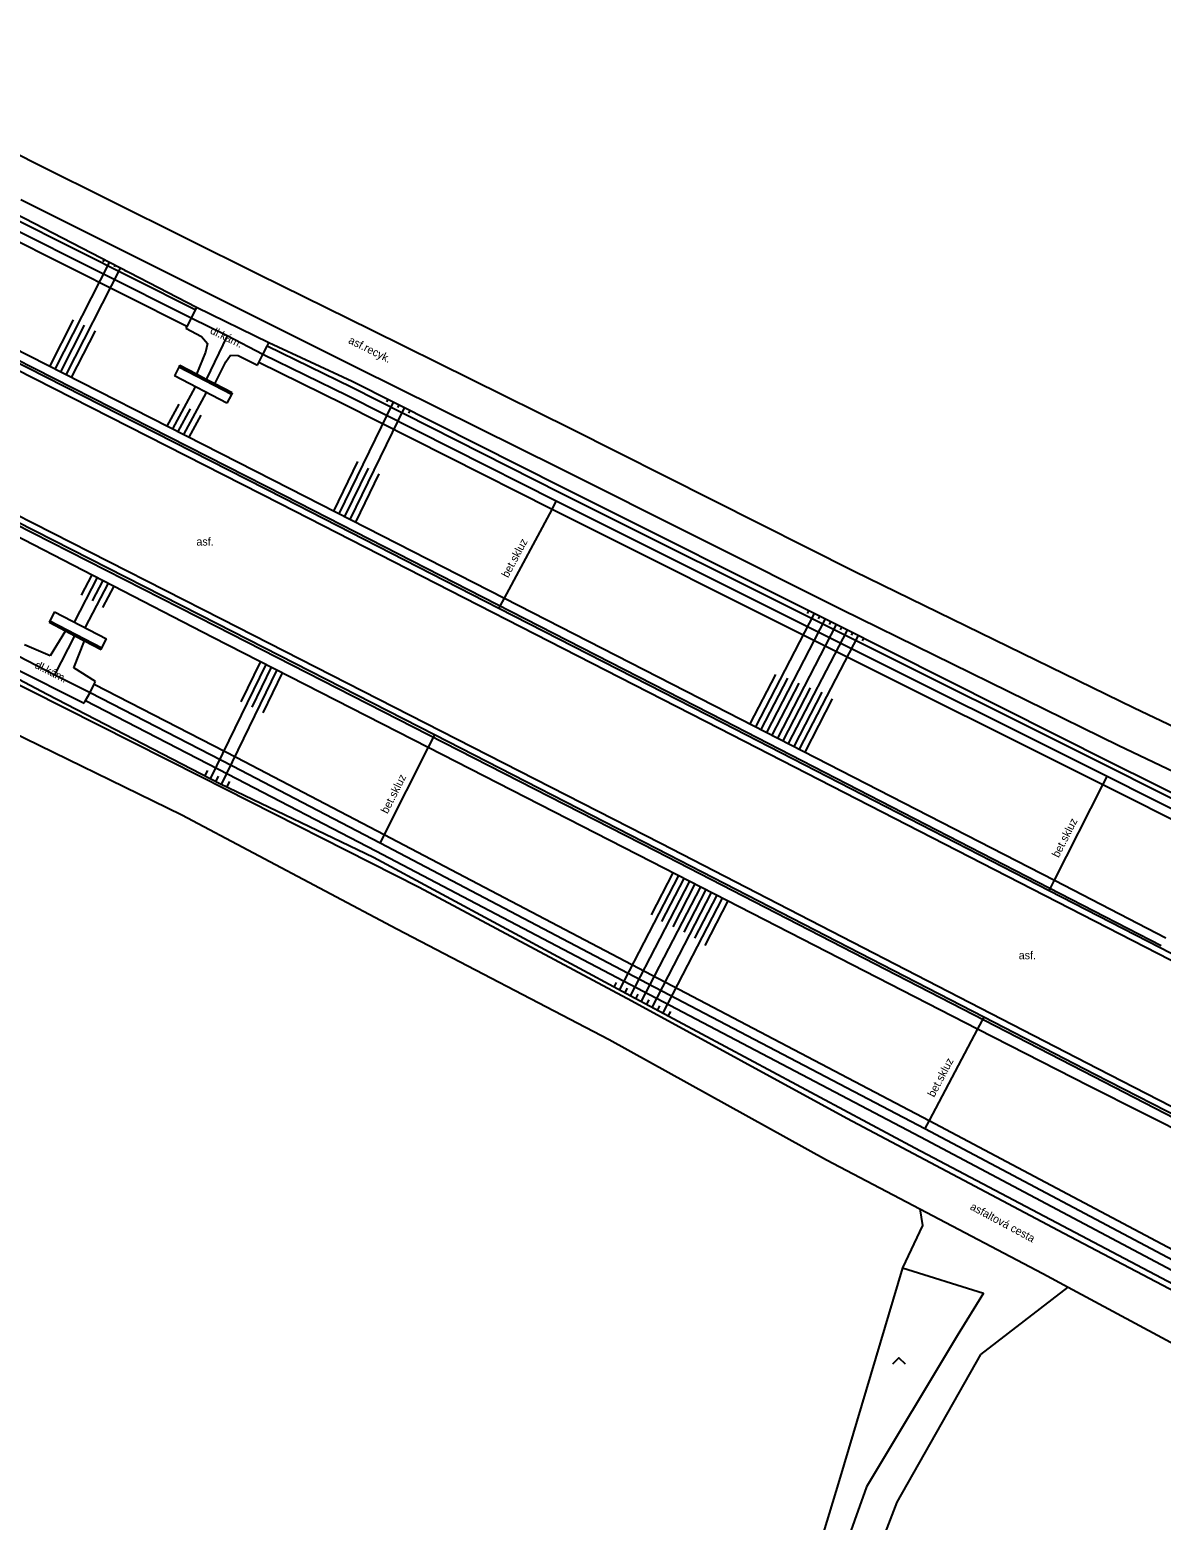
# Model space of a CAD drawing. Extents: x -539244 to -537359, y -1183785 to -1181851.
# Drawn here: x -538474.3 to -538382.4, y -1182902.8 to -1182781.7 of the extents above; entities that cross this region are included whole.
import ezdxf

# ---------------------------------------------------------------- set-up
doc = ezdxf.new("R2010")
doc.units = 0
for name, color, linetype in [('Vrstva 10', 7, 'Continuous'), ('Vrstva 11', 7, 'Continuous'), ('Vrstva 14', 7, 'Continuous'), ('Vrstva 15', 7, 'Continuous'), ('Vrstva 21', 7, 'Continuous'), ('Vrstva 36', 7, 'Continuous'), ('Vrstva 40', 7, 'Continuous'), ('Vrstva 9', 7, 'Continuous')]:
    doc.layers.add(name, color=color, linetype=linetype)

msp = doc.modelspace()

# ---------------------------------------------------------------- linework, layer by layer
at = {"layer": 'Vrstva 10'}
for p, q in [((-538489.631, -1182802.063), (-538453.977, -1182820.153)), ((-538458.743, -1182829.553), (-538494.407, -1182811.446)), ((-538453.977, -1182820.153), (-538418.301, -1182838.412)), ((-538423.066, -1182847.775), (-538458.743, -1182829.553)), ((-538418.301, -1182838.412), (-538382.698, -1182856.699)), ((-538387.534, -1182866.074), (-538423.066, -1182847.775)), ((-538382.698, -1182856.699), (-538347.199, -1182875.039)), ((-538351.928, -1182884.425), (-538387.534, -1182866.074))]:
    msp.add_line(p, q, dxfattribs=at)
at = {"layer": 'Vrstva 11'}
for p, q in [((-538495.381, -1182781.683), (-538473.693, -1182792.597)), ((-538473.693, -1182792.597), (-538455.751, -1182801.544)), ((-538457.128, -1182804.455), (-538475.061, -1182795.493)), ((-538460.885, -1182804.439), (-538475.768, -1182796.967)), ((-538461.569, -1182805.774), (-538476.446, -1182798.305)), ((-538455.751, -1182801.544), (-538446.57, -1182806.067)), ((-538454.912, -1182807.118), (-538460.787, -1182804.249)), ((-538447.711, -1182809.176), (-538457.128, -1182804.455)), ((-538461.642, -1182805.916), (-538460.386, -1182806.606)), ((-538446.57, -1182806.067), (-538430.372, -1182814.08)), ((-538460.386, -1182806.606), (-538459.885, -1182807.165)), ((-538459.885, -1182807.165), (-538460.05, -1182807.864)), ((-538448.175, -1182810.748), (-538455.046, -1182807.382)), ((-538460.05, -1182807.864), (-538460.797, -1182809.658)), ((-538459.29, -1182810.442), (-538458.395, -1182808.642)), ((-538458.395, -1182808.642), (-538458.033, -1182808.1)), ((-538458.033, -1182808.1), (-538457.395, -1182808.131)), ((-538457.395, -1182808.131), (-538455.829, -1182808.93)), ((-538448.843, -1182812.092), (-538455.723, -1182808.721)), ((-538458.322, -1182812.015), (-538462.579, -1182809.803)), ((-538457.953, -1182811.305), (-538462.21, -1182809.093)), ((-538431.382, -1182817.268), (-538447.711, -1182809.176)), ((-538431.213, -1182819.315), (-538448.175, -1182810.748)), ((-538431.887, -1182820.655), (-538448.843, -1182812.092)), ((-538430.372, -1182814.08), (-538407.338, -1182825.669)), ((-538408.354, -1182828.793), (-538431.382, -1182817.268)), ((-538408.747, -1182830.537), (-538431.213, -1182819.315)), ((-538409.417, -1182831.879), (-538431.887, -1182820.655)), ((-538407.338, -1182825.669), (-538384.592, -1182836.775)), ((-538472.33, -1182828.973), (-538468.1, -1182831.168)), ((-538385.827, -1182839.854), (-538408.354, -1182828.793)), ((-538472.699, -1182829.683), (-538468.469, -1182831.878)), ((-538471.442, -1182830.504), (-538472.667, -1182832.544)), ((-538386.455, -1182841.675), (-538408.747, -1182830.537)), ((-538472.667, -1182832.544), (-538474.756, -1182831.645)), ((-538470.753, -1182833.522), (-538469.885, -1182831.312)), ((-538387.127, -1182843.017), (-538409.417, -1182831.879)), ((-538460.441, -1182842.376), (-538477.999, -1182833.509)), ((-538475.727, -1182833.456), (-538469.918, -1182836.378)), ((-538468.983, -1182834.631), (-538470.753, -1182833.522)), ((-538469.096, -1182834.841), (-538457.517, -1182840.808)), ((-538469.804, -1182836.165), (-538458.207, -1182842.14)), ((-538384.592, -1182836.775), (-538361.115, -1182847.877)), ((-538479.69, -1182836.826), (-538461.985, -1182845.451)), ((-538362.461, -1182850.949), (-538385.827, -1182839.854)), ((-538457.517, -1182840.808), (-538445.524, -1182847.048)), ((-538442.702, -1182851.367), (-538460.441, -1182842.376)), ((-538458.207, -1182842.14), (-538446.209, -1182848.383)), ((-538363.328, -1182853.284), (-538386.455, -1182841.675)), ((-538364.002, -1182854.624), (-538387.127, -1182843.017)), ((-538461.985, -1182845.451), (-538444.501, -1182854.716)), ((-538445.524, -1182847.048), (-538424.319, -1182858.183)), ((-538446.209, -1182848.383), (-538425.015, -1182859.511)), ((-538425.404, -1182860.593), (-538442.702, -1182851.367)), ((-538444.501, -1182854.716), (-538427.254, -1182863.712)), ((-538424.319, -1182858.183), (-538401.242, -1182870.277)), ((-538425.015, -1182859.511), (-538401.942, -1182871.603)), ((-538407.94, -1182870.134), (-538425.404, -1182860.593)), ((-538427.254, -1182863.712), (-538409.594, -1182873.474)), ((-538352.202, -1182884.876), (-538387.783, -1182866.536)), ((-538390.295, -1182879.474), (-538407.94, -1182870.134)), ((-538401.242, -1182870.277), (-538379.033, -1182882.058)), ((-538401.942, -1182871.603), (-538379.737, -1182883.384)), ((-538373.288, -1182888.418), (-538390.295, -1182879.474)), ((-538403.42, -1182882.26), (-538396.84, -1182884.3)), ((-538397.04, -1182889.29), (-538389.965, -1182883.816)), ((-538396.84, -1182884.3), (-538398.97, -1182887.78)), ((-538398.97, -1182887.78), (-538406.33, -1182900.03)), ((-538403.86, -1182901.3), (-538397.04, -1182889.29)), ((-538406.33, -1182900.03), (-538415.89, -1182926.8)), ((-538413.81, -1182927.3), (-538403.86, -1182901.3))]:
    msp.add_line(p, q, dxfattribs=at)
for points in [[(-538453.722, -1182819.731), (-538480.448, -1182806.147), (-538489.405, -1182801.595)], [(-538460.787, -1182804.249), (-538460.885, -1182804.439), (-538461.208, -1182805.116), (-538461.569, -1182805.774), (-538461.642, -1182805.916)], [(-538455.829, -1182808.93), (-538455.723, -1182808.721), (-538455.392, -1182808.048), (-538455.046, -1182807.382), (-538454.912, -1182807.118)], [(-538462.141, -1182808.96), (-538462.21, -1182809.093), (-538462.579, -1182809.803)], [(-538457.884, -1182811.172), (-538459.29, -1182810.442), (-538459.992, -1182810.077), (-538460.797, -1182809.658), (-538462.141, -1182808.96)], [(-538457.884, -1182811.172), (-538457.953, -1182811.305), (-538458.322, -1182812.015)], [(-538459.1, -1182829.941), (-538485.794, -1182816.371), (-538494.666, -1182811.861)], [(-538418.052, -1182837.967), (-538436.208, -1182828.685), (-538453.722, -1182819.731)], [(-538472.33, -1182828.973), (-538472.699, -1182829.683), (-538472.768, -1182829.816)], [(-538472.768, -1182829.816), (-538471.442, -1182830.504), (-538470.671, -1182830.904), (-538469.885, -1182831.312), (-538468.538, -1182832.011)], [(-538423.368, -1182848.208), (-538441.45, -1182838.964), (-538459.1, -1182829.941)], [(-538468.538, -1182832.011), (-538468.469, -1182831.878), (-538468.1, -1182831.168)], [(-538469.918, -1182836.378), (-538469.804, -1182836.165), (-538469.419, -1182835.519), (-538469.096, -1182834.841), (-538468.983, -1182834.631)], [(-538382.485, -1182856.261), (-538391.507, -1182851.621), (-538418.052, -1182837.967)], [(-538387.783, -1182866.536), (-538396.812, -1182861.886), (-538423.368, -1182848.208)], [(-538346.958, -1182874.603), (-538346.996, -1182874.583), (-538382.485, -1182856.261)], [(-538409.594, -1182873.474), (-538402.011, -1182877.46), (-538392.009, -1182882.718)], [(-538402.011, -1182877.46), (-538401.79, -1182878.82), (-538403.42, -1182882.26)], [(-538392.009, -1182882.718), (-538389.965, -1182883.816), (-538375.09, -1182891.807)]]:
    msp.add_lwpolyline(points, dxfattribs=at)
at = {"layer": 'Vrstva 14'}
for p, q in [((-538460.787, -1182804.249), (-538475.557, -1182796.594)), ((-538461.208, -1182805.116), (-538476.105, -1182797.637)), ((-538458.297, -1182806.536), (-538461.208, -1182805.116)), ((-538458.297, -1182806.536), (-538459.992, -1182810.077)), ((-538455.392, -1182808.048), (-538458.297, -1182806.536)), ((-538448.13, -1182810.251), (-538454.912, -1182807.118)), ((-538448.509, -1182811.42), (-538455.392, -1182808.048)), ((-538431.098, -1182818.824), (-538448.13, -1182810.251)), ((-538431.55, -1182819.985), (-538448.509, -1182811.42)), ((-538408.793, -1182829.99), (-538431.098, -1182818.824)), ((-538409.082, -1182831.208), (-538431.55, -1182819.985)), ((-538472.928, -1182835.682), (-538490.861, -1182826.18)), ((-538436.208, -1182828.685), (-538435.764, -1182827.856)), ((-538386.446, -1182841.225), (-538408.793, -1182829.99)), ((-538472.302, -1182834.08), (-538470.671, -1182830.904)), ((-538386.791, -1182842.346), (-538409.082, -1182831.208)), ((-538475.264, -1182832.53), (-538472.302, -1182834.08)), ((-538472.302, -1182834.08), (-538469.419, -1182835.519)), ((-538469.419, -1182835.519), (-538457.862, -1182841.474)), ((-538458.844, -1182842.954), (-538472.928, -1182835.682)), ((-538441.45, -1182838.964), (-538441.956, -1182839.968)), ((-538441.956, -1182839.968), (-538445.524, -1182847.048)), ((-538457.862, -1182841.474), (-538445.862, -1182847.718)), ((-538363.414, -1182852.724), (-538386.446, -1182841.225)), ((-538363.665, -1182853.954), (-538386.791, -1182842.346)), ((-538446.41, -1182848.907), (-538458.844, -1182842.954)), ((-538445.524, -1182847.048), (-538445.862, -1182847.718)), ((-538445.862, -1182847.718), (-538424.667, -1182858.847)), ((-538425.493, -1182860.19), (-538446.41, -1182848.907)), ((-538391.507, -1182851.621), (-538391.076, -1182850.773)), ((-538424.667, -1182858.847), (-538401.592, -1182870.94)), ((-538402.421, -1182872.533), (-538425.493, -1182860.19)), ((-538396.812, -1182861.886), (-538397.311, -1182862.832)), ((-538388.26, -1182867.47), (-538352.414, -1182885.451)), ((-538401.592, -1182870.94), (-538379.385, -1182882.721)), ((-538380.364, -1182884.152), (-538402.421, -1182872.533))]:
    msp.add_line(p, q, dxfattribs=at)
for points in [[(-538488.966, -1182800.758), (-538480.02, -1182805.308), (-538453.209, -1182818.943)], [(-538495.104, -1182812.627), (-538486.219, -1182817.21), (-538459.455, -1182831.015)], [(-538453.209, -1182818.943), (-538435.764, -1182827.856), (-538417.613, -1182837.129)], [(-538435.764, -1182827.856), (-538431.887, -1182820.655), (-538431.55, -1182819.985)], [(-538459.455, -1182831.015), (-538441.956, -1182839.968), (-538423.803, -1182849.256)], [(-538417.613, -1182837.129), (-538391.076, -1182850.773), (-538382.012, -1182855.433)], [(-538391.076, -1182850.773), (-538387.127, -1182843.017), (-538386.791, -1182842.346)], [(-538423.803, -1182849.256), (-538397.311, -1182862.832), (-538388.26, -1182867.47)], [(-538397.311, -1182862.832), (-538401.242, -1182870.277), (-538401.592, -1182870.94)]]:
    msp.add_lwpolyline(points, dxfattribs=at)
at = {"layer": 'Vrstva 15'}
for p, q in [((-538468.373, -1182800.513), (-538468.294, -1182800.358)), ((-538472.269, -1182809.25), (-538467.849, -1182800.589)), ((-538471.378, -1182809.703), (-538466.962, -1182801.049)), ((-538467.462, -1182800.93), (-538467.405, -1182800.819)), ((-538466.557, -1182801.357), (-538466.517, -1182801.279)), ((-538472.715, -1182809.023), (-538470.792, -1182805.255)), ((-538471.823, -1182809.476), (-538469.888, -1182805.684)), ((-538470.931, -1182809.93), (-538468.996, -1182806.137)), ((-538460.897, -1182810.677), (-538462.738, -1182814.097)), ((-538460.01, -1182811.138), (-538461.847, -1182814.55)), ((-538462.224, -1182812.085), (-538463.184, -1182813.87)), ((-538461.294, -1182812.469), (-538462.292, -1182814.324)), ((-538449.179, -1182821.002), (-538444.773, -1182811.941)), ((-538448.288, -1182821.457), (-538443.879, -1182812.391)), ((-538445.312, -1182811.908), (-538445.219, -1182811.716)), ((-538444.419, -1182812.358), (-538444.326, -1182812.166)), ((-538460.435, -1182812.984), (-538461.4, -1182814.777)), ((-538443.536, -1182812.827), (-538443.433, -1182812.615)), ((-538449.624, -1182820.775), (-538447.67, -1182816.757)), ((-538448.733, -1182821.23), (-538446.82, -1182817.297)), ((-538447.843, -1182821.685), (-538445.937, -1182817.765)), ((-538470.712, -1182829.813), (-538468.822, -1182826.183)), ((-538470.131, -1182827.614), (-538469.267, -1182825.954)), ((-538469.825, -1182830.273), (-538467.934, -1182826.641)), ((-538469.247, -1182828.081), (-538468.378, -1182826.412)), ((-538468.393, -1182828.606), (-538467.489, -1182826.871)), ((-538415.338, -1182838.299), (-538410.575, -1182829.098)), ((-538411.138, -1182829.097), (-538411.023, -1182828.874)), ((-538410.24, -1182829.539), (-538410.128, -1182829.322)), ((-538414.449, -1182838.756), (-538409.681, -1182829.545)), ((-538413.559, -1182839.213), (-538408.787, -1182829.993)), ((-538412.67, -1182839.67), (-538407.894, -1182830.442)), ((-538409.343, -1182829.98), (-538409.234, -1182829.769)), ((-538408.446, -1182830.422), (-538408.34, -1182830.218)), ((-538407.549, -1182830.865), (-538407.447, -1182830.667)), ((-538411.781, -1182840.127), (-538407, -1182830.891)), ((-538406.659, -1182831.318), (-538406.554, -1182831.116)), ((-538457.156, -1182836.264), (-538455.57, -1182833.003)), ((-538459.652, -1182842.537), (-538455.126, -1182833.23)), ((-538458.761, -1182842.994), (-538454.235, -1182833.686)), ((-538456.262, -1182836.711), (-538454.68, -1182833.458)), ((-538455.373, -1182837.168), (-538453.79, -1182833.913)), ((-538415.783, -1182838.07), (-538413.705, -1182834.056)), ((-538414.893, -1182838.527), (-538412.735, -1182834.358)), ((-538414.004, -1182838.984), (-538411.811, -1182834.747)), ((-538413.115, -1182839.442), (-538410.881, -1182835.126)), ((-538412.226, -1182839.899), (-538409.941, -1182835.486)), ((-538411.337, -1182840.356), (-538409.103, -1182836.04)), ((-538460.096, -1182842.308), (-538459.87, -1182841.844)), ((-538459.207, -1182842.766), (-538458.992, -1182842.324)), ((-538458.31, -1182843.209), (-538458.081, -1182842.738)), ((-538426.412, -1182859.694), (-538421.595, -1182850.387)), ((-538425.532, -1182860.169), (-538420.705, -1182850.843)), ((-538424.651, -1182860.641), (-538419.815, -1182851.299)), ((-538423.815, -1182853.589), (-538422.04, -1182850.159)), ((-538422.962, -1182854.115), (-538421.151, -1182850.615)), ((-538422.06, -1182854.548), (-538420.261, -1182851.071)), ((-538423.769, -1182861.113), (-538418.925, -1182851.756)), ((-538422.887, -1182861.584), (-538418.036, -1182852.211)), ((-538421.154, -1182854.972), (-538419.371, -1182851.527)), ((-538420.292, -1182855.483), (-538418.48, -1182851.984)), ((-538419.463, -1182856.056), (-538417.591, -1182852.44)), ((-538426.853, -1182859.457), (-538426.654, -1182859.072)), ((-538425.973, -1182859.931), (-538425.767, -1182859.533)), ((-538425.092, -1182860.405), (-538424.895, -1182860.024)), ((-538424.21, -1182860.876), (-538424, -1182860.47)), ((-538423.328, -1182861.348), (-538423.136, -1182860.977)), ((-538422.446, -1182861.82), (-538422.24, -1182861.423))]:
    msp.add_line(p, q, dxfattribs=at)
at = {"layer": 'Vrstva 21'}
for p, q in [((-538403.42, -1182882.26), (-538408.56, -1182899.53)), ((-538408.56, -1182899.53), (-538416.95, -1182927.29))]:
    msp.add_line(p, q, dxfattribs=at)
at = {"layer": 'Vrstva 36'}
msp.add_lwpolyline([(-538404.211, -1182890.065), (-538403.711, -1182889.565), (-538403.211, -1182890.065)], dxfattribs=at)
at = {"layer": 'Vrstva 9'}
for p, q in [((-538453.631, -1182819.553), (-538489.321, -1182801.413)), ((-538494.757, -1182812.039), (-538459.191, -1182830.119)), ((-538417.961, -1182837.789), (-538453.631, -1182819.553)), ((-538459.191, -1182830.119), (-538423.459, -1182848.386)), ((-538382.394, -1182856.083), (-538417.961, -1182837.789)), ((-538423.459, -1182848.386), (-538387.875, -1182866.714)), ((-538387.875, -1182866.714), (-538352.294, -1182885.054))]:
    msp.add_line(p, q, dxfattribs=at)

# ---------------------------------------------------------------- texts
at = {"layer": 'Vrstva 40'}
for s, rotation, p in [('dl.kám.', 333.97187, (-538459.739, -1182806.319)), ('asf.recyk.', 333.63882, (-538448.502, -1182807.11)), ('bet.skluz', 61.8353, (-538435.47, -1182826.248)), ('dl.kám.', 333.29703, (-538473.993, -1182833.489)), ('bet.skluz', 63.25198, (-538445.262, -1182845.416)), ('bet.skluz', 63.04832, (-538390.728, -1182848.986)), ('bet.skluz', 62.16848, (-538400.842, -1182868.447)), ('asfaltová cesta', 331.87626, (-538397.984, -1182877.476))]:
    msp.add_text(s, height=0.65, rotation=rotation, dxfattribs=at).set_placement(p)
for p in [(-538460.794, -1182823.581), (-538393.971, -1182857.184)]:
    msp.add_text('asf.', height=0.65, dxfattribs=at).set_placement(p)

doc.saveas('drawing.dxf')
